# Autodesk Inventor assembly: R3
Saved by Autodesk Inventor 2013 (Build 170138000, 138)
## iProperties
Created: 2021-02
Part Number: R3
Document SubType Name: Assembly
Designer: Fede
Author: Fede
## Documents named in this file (2)
- C:\0000 FEDE\16GB\0000 INTERIOR\DE_TMP_BAS\BAS_DTON - demora conexion al energizar\pcb\BOR\turn on\Imported Components\BAS_DTON\R3.iam
- C:\0000 FEDE\16GB\0000 INTERIOR\DE_TMP_BAS\BAS_DTON - demora conexion al energizar\pcb\BOR\turn on\Imported Components\BAS_DTON\MFR-25_300mils_1.iam
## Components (1 placed, 1 different names)
1. MFR-25_300mils_1:1 [sub-assembly]
